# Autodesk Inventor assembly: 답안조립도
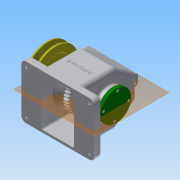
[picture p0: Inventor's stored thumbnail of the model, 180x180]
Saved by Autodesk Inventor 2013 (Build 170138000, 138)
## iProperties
Created: 2016-12
Part Number: 답안조립도
Document SubType Name: Assembly
Designer: Administrator
Author: Administrator
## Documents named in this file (13)
- C:\Users\Administrator\Desktop\461208V1028\답안조립도.iam
- C:\Users\Administrator\Desktop\461208V1028\부품1.ipt
- C:\Users\Administrator\Desktop\461208V1028\V-벨트풀리.ipt
- C:\Users\Administrator\Desktop\461208V1028\멈춤나사 - M4x10.ipt
- C:\Users\Administrator\Desktop\461208V1028\축.ipt
- C:\Users\Administrator\Desktop\461208V1028\키 - 5 x 5 x 18.ipt
- C:\Users\Administrator\Desktop\461208V1028\뒤커버.ipt
- C:\Users\Administrator\Desktop\461208V1028\앞커버.ipt
- C:\Users\Administrator\Desktop\461208V1028\오일씰 28 40 8.ipt
- C:\Users\Administrator\Desktop\461208V1028\볼트 M3 x 8.ipt
- C:\Users\Administrator\Desktop\461208V1028\베어링 6203.ipt
- C:\Users\Administrator\Desktop\461208V1028\스퍼기어.ipt
- C:\Users\Administrator\Desktop\461208V1028\키 - 6 x 6 x 22.ipt
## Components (9 placed, 2 different names)
1. V-벨트풀리:1
2. ISO 4762 M3 x 8:1
3. ISO 4762 M3 x 8:2
4. ISO 4762 M3 x 8:3
5. ISO 4762 M3 x 8:4
6. ISO 4762 M3 x 8:5
7. ISO 4762 M3 x 8:6
8. ISO 4762 M3 x 8:7
9. ISO 4762 M3 x 8:8
